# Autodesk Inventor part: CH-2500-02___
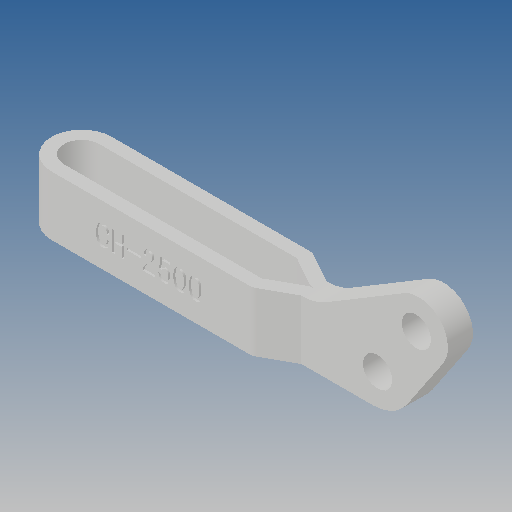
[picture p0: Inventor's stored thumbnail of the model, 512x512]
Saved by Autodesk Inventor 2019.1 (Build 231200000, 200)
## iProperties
Created: 2012-09
Part Number: CH-2500-02___
Material: Ogólny
Document SubType Name: Modeling
Designer: CADENGINEERING4
Density: 1 g/cm^3
Appearance: Domyślna
Author: CADENGINEERING4
Revision Number: ÈÎºÎ
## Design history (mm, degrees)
feature "NONE"
node "Bryła1"
